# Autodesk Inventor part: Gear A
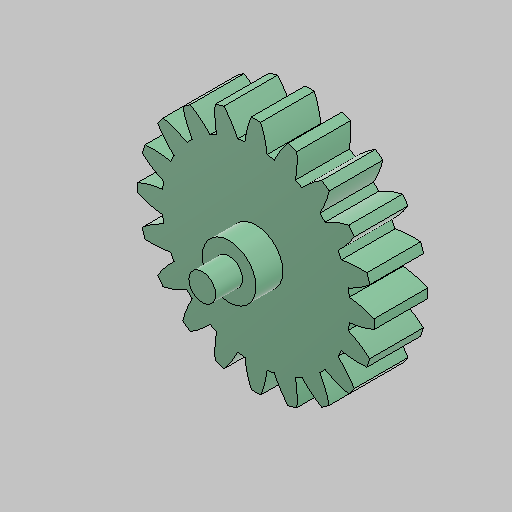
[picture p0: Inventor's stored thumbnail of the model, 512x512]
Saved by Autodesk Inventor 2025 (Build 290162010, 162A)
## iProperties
Created: 2024-10
Part Number: Gear A
Material: Generic
Document SubType Name: Modeling
Designer: Dennis
Mass: 12.9565 g
Surface Area: 52.5838 cm^2
Volume: 12.9565 cm^3
Density: 1 g/cm^3
Appearance: Smooth - Dark Sea Green
Author: Dennis
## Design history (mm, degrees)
sketch "Sketch1"
  geometry: L1 (0, 0)-(22, 0); L2 (22, 0)-(22, 10); L3 (22, 10)-(5, 10); L4 (5, 10)-(5, 15); L5 (5, 15)-(2.5, 15); L6 (2.5, 15)-(2.5, 20); L7 (2.5, 20)-(0, 20); L8 (0, 20)-(0, 0)
  constraints: 16 end point, 7 perpendicular, 1 horizontal
  dimensions: "d0" = 10 distance between parallel lines of L1 L3; "d1" = 5 distance between parallel lines of L3 L5; "d2" = 5 distance between parallel lines of L7 L5; "d3" = 44 diameter of L2 L8; "d4" = 5 diameter of L6 L8; "d5" = 10 diameter of L4 L8
revolve "Revolution1" sketch "Sketch1" stored, may be unused: angle "d6" = 90 deg
sketch "Sketch2"
  geometry: C1 r 20 at (0, 0); 1 further point
  constraints: 1 centre point, 1 coincident
  dimensions: "d7" = 40 diameter of C1
extrude_surface "ExtrusionSrf1" sketch "Sketch2" dims "d8" = 10, "d9" = 0
node "Spur Gear Teeth1"
body "Solid1"
body "Srf1"
feature "Spur Gear1"
